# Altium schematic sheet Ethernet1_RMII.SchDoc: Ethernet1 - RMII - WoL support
size A3; Project: Project name; Date: Not used; ApprovedBy: Not used; CheckedBy: Not used; Author: Not used; CompanyName: STMicroelectronics; DrawnBy: Not used; Engineer: Not used; Organization: Not used; Address1: Not used; Address2: Not used; Address3: Not used; Address4: Not used; DocumentNumber: 7; Revision: Not used; SheetNumber: 7; SheetTotal: 17
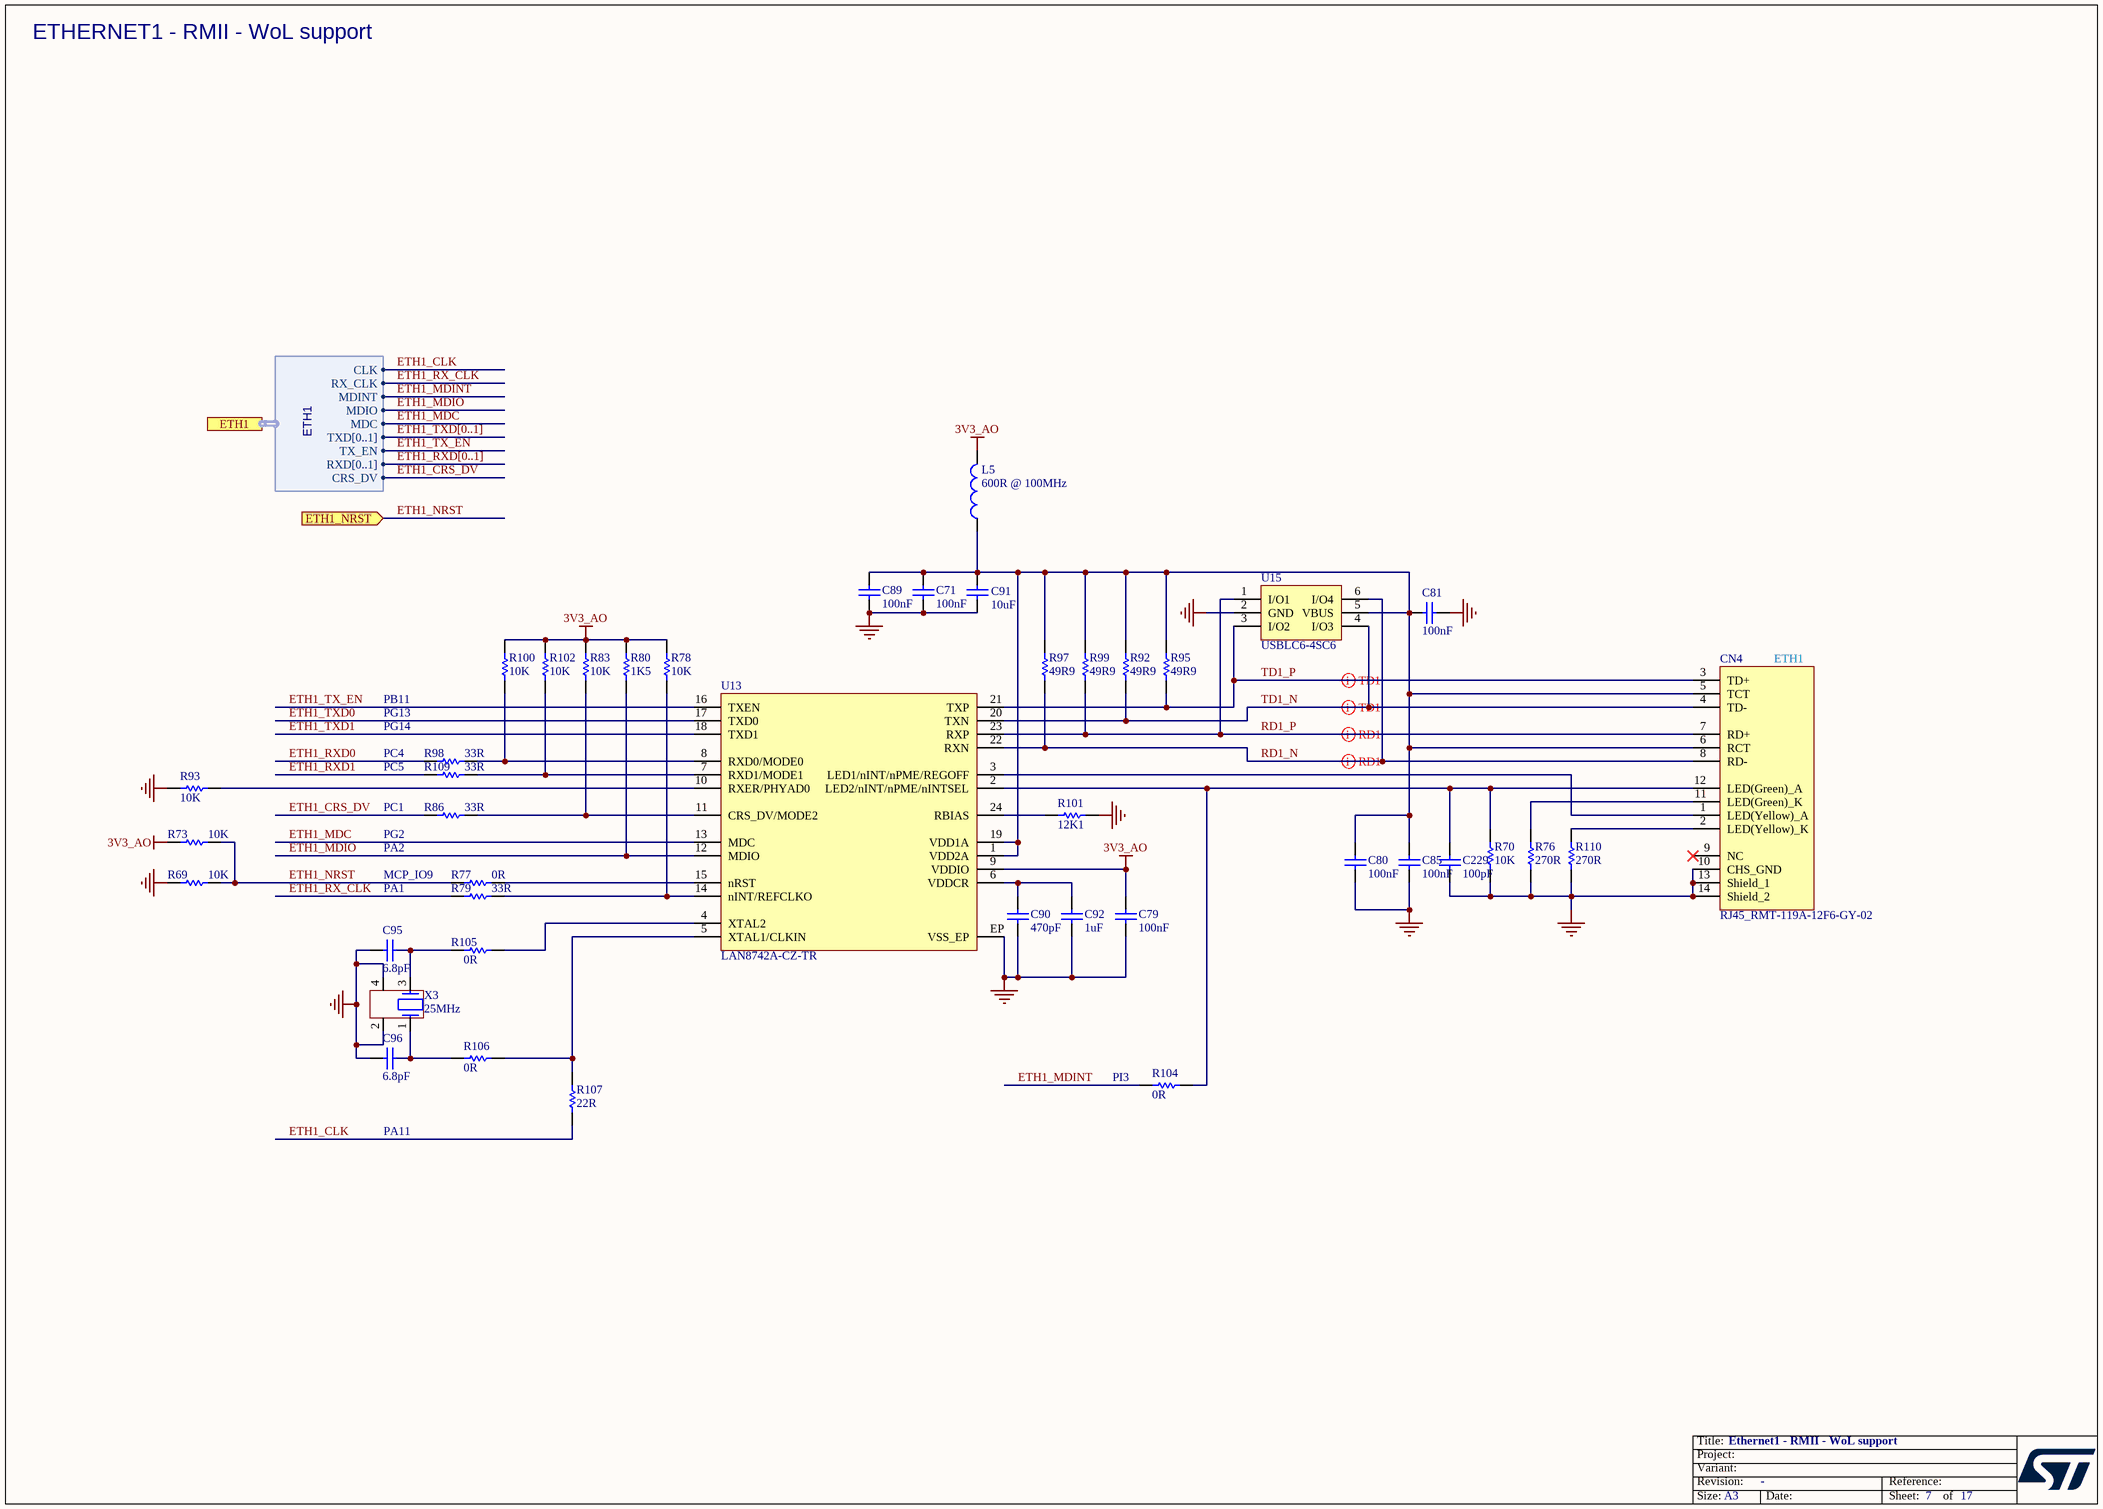
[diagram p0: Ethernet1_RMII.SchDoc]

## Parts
C71  value 100nF  [C0402]  (hidden comment: Capacitor)
C79  value 100nF  [C0402]  (hidden comment: Capacitor)
C80  value 100nF  [C0402]  (hidden comment: Capacitor)
C81  value 100nF  [C0402]  (hidden comment: Capacitor)
C85  value 100nF  [C0402]  (hidden comment: Capacitor)
C89  value 100nF  [C0402]  (hidden comment: Capacitor)
C90  value 470pF  [C0402]  (hidden comment: Capacitor)
C91  value 10uF  [C0603]  (hidden comment: Capacitor)
C92  value 1uF  [C0201_MURATA_GRM033_H0P3]  (hidden comment: Capacitor)
C95  value 6.8pF  [C0402]  (hidden comment: Capacitor)
C96  value 6.8pF  [C0402]  (hidden comment: Capacitor)
C229  value 100pF  [C0402]  (hidden comment: Capacitor)
CN4  value RJ45_RMT-119A-12F6-GY-02  [CON_RJ45_PHC_RMT-119A-12F6-GY-02]  (hidden comment: RJ45_RTS-119A-12F6-GY-02)
L5  value 600R @ 100MHz  [L0603]  (hidden comment: BEAD)
R69  value 10K  [R0402]  (hidden comment: Resistor)
R70  value 10K  [R0402]  (hidden comment: Resistor)
R73  value 10K  [R0402]  (hidden comment: Resistor)
R76  value 270R  [R0402]  (hidden comment: Resistor)
R77  value 0R  [R0402]  (hidden comment: Resistor)
R78  value 10K  [R0402]  (hidden comment: Resistor)
R79  value 33R  [R0402]  (hidden comment: Resistor)
R80  value 1K5  [R0402]  (hidden comment: Resistor)
R83  value 10K  [R0402]  (hidden comment: Resistor)
R86  value 33R  [R0402]  (hidden comment: Resistor)
R92  value 49R9  [R0402]  (hidden comment: Resistor)
R93  value 10K  [R0402]  (hidden comment: Resistor)
R95  value 49R9  [R0402]  (hidden comment: Resistor)
R97  value 49R9  [R0402]  (hidden comment: Resistor)
R98  value 33R  [R0402]  (hidden comment: Resistor)
R99  value 49R9  [R0402]  (hidden comment: Resistor)
R100  value 10K  [R0402]  (hidden comment: Resistor)
R101  value 12K1  [R0402]  (hidden comment: Resistor)
R102  value 10K  [R0402]  (hidden comment: Resistor)
R104  value 0R  [R0402]  (hidden comment: Resistor)
R105  value 0R  [R0402]  (hidden comment: Resistor)
R106  value 0R  [R0402]  (hidden comment: Resistor)
R107  value 22R  [R0402]  (hidden comment: Resistor)
R109  value 33R  [R0402]  (hidden comment: Resistor)
R110  value 270R  [R0402]  (hidden comment: Resistor)
U13  LAN8742A-CZ-TR  [ICC_VQFN24-EPAD_4X4_P050]
U15  USBLC6-4SC6  [ESD_SOT23-6L]
X3  value 25MHz  [CRY_NX2016SA_4P]  (hidden comment: XTAL_4_PINS)

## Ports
ETH1 (harness ETH1), ETH1_NRST (in)

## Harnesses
ETH1: MDINT, TXD[0..1], MDIO, MDC, RX_CLK, TX_EN, RXD[0..1], CRS_DV, CLK

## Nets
3V3_AO: C79.2 L5.2 R73.2 R78.2 R80.2 R83.2 R100.2 R102.2 U13.9(VDDIO)
GND: C71.1 C79.1 C80.1 C81.2 C85.1 C89.1 C90.1 C91.2 C92.1 C95.1 C96.1 C229.1 CN4.10(CHS_GND) CN4.13(Shield_1) CN4.14(Shield_2) R69.2 R70.1 R76.1 R93.2 R101.2 R110.1 U13.EP(VSS_EP) U15.2(GND) X3.2 X3.4
ETH1_CLK: R107.1 ; port ETH1.CLK
ETH1_CRS_DV: R86.1 ; port ETH1.CRS_DV
ETH1_MDC: U13.13(MDC) ; port ETH1.MDC
ETH1_MDINT: R104.1 ; port ETH1.MDINT
ETH1_MDIO: R80.1 U13.12(MDIO) ; port ETH1.MDIO
ETH1_NRST: R69.1 R73.1 R77.1 ; port ETH1_NRST
ETH1_RX_CLK: R79.1 ; port ETH1.RX_CLK
ETH1_RXD0: R98.1
ETH1_RXD1: R109.1
ETH1_TX_EN: U13.16(TXEN) ; port ETH1.TX_EN
ETH1_TXD0: U13.17(TXD0)
ETH1_TXD1: U13.18(TXD1)
RD1_N: CN4.8(RD-) R97.1 U13.22(RXN) U15.6(I/O4)
RD1_P: CN4.7(RD+) R99.1 U13.23(RXP) U15.1(I/O1)
TD1_N: CN4.4(TD-) R92.1 U13.20(TXN) U15.4(I/O3)
TD1_P: CN4.3(TD+) R95.1 U13.21(TXP) U15.3(I/O2)
NetC71_2: C71.2 C80.2 C81.1 C85.2 C89.2 C91.1 CN4.5(TCT) CN4.6(RCT) L5.1 R92.2 R95.2 R97.2 R99.2 U13.1(VDD2A) U13.19(VDD1A) U15.5(VBUS)
NetC90_2: C90.2 C92.2 U13.6(VDDCR)
NetC95_2: C95.2 R105.1 X3.3
NetC96_2: C96.2 R106.1 X3.1
NetC229_2: C229.2 CN4.12(LED(Green)_A) R70.2 R104.2 U13.2(LED2/nINT/nPME/nINTSEL)
NetCN4_1: CN4.1(LED(Yellow)_A) U13.3(LED1/nINT/nPME/REGOFF)
NetCN4_2: CN4.2(LED(Yellow)_K) R110.2
NetCN4_11: CN4.11(LED(Green)_K) R76.2
NetR77_2: R77.2 U13.15(nRST)
NetR78_1: R78.1 R79.2 U13.14(nINT/REFCLKO)
NetR83_1: R83.1 R86.2 U13.11(CRS_DV/MODE2)
NetR93_1: R93.1 U13.10(RXER/PHYAD0)
NetR98_2: R98.2 R100.1 U13.8(RXD0/MODE0)
NetR101_1: R101.1 U13.24(RBIAS)
NetR102_1: R102.1 R109.2 U13.7(RXD1/MODE1)
NetR105_2: R105.2 U13.4(XTAL2)
NetR106_2: R106.2 R107.2 U13.5(XTAL1/CLKIN)

Not connected (* = marked no-connect by the designer): CN4 9(NC)*

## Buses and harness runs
bus ETH1_RXD[0..1]
bus ETH1_TXD[0..1]

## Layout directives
differential pair: RD1_N, RD1_P, TD1_N, TD1_P

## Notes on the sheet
- ETHERNET1 - RMII - WoL support
- PB11
- PG13
- ETH1
- PC4
- PC5
- PG14
- PC1
- (near R86) PG2
- PA2
- PA1
- MCP_IO9
- (near R104) PI3
- PA11

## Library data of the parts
C71 C79-C81 C85 C89 = MCD-00006: Capacitor, MLCC, 100nF, 16V, X7R, +/-10%, 0402, T=0.5mm; Manufacturer_Part_Number: CC0402KRX7R7BB104; Manufacturer: YAGEO; Part_Preference: Recommended; Partial_Alternate_Internal_Part_Number: MCD-03299; Order_Code_RS: 9402047; Component_Country_Of_Origin: China; ShowFields: YES; ID: 2474
C90 = MCD-00724: Capacitor, MLCC, 470pF, 50V, NPO, +/-5%, 0402, T=0.5mm; Manufacturer_Part_Number: CC0402JRNPO9BN471; Manufacturer: YAGEO; Part_Preference: Recommended; Order_Code_RS: 199-2186; Component_Country_Of_Origin: China; ShowFields: YES; ID: 3023
C91 = MCD-00099: Capacitor, MLCC, 10uF, 10V, X5R, +/-10%, 0603, T=0.8mm; Manufacturer_Part_Number: GRM188R61A106KE69; Manufacturer: MURATA; Part_Preference: Recommended; Partial_Alternate_Internal_Part_Number: MCD-03152; Order_Code_RS: 2494233; Component_Country_Of_Origin: Japan°°; ShowFields: YES; ID: 2770
C92 = MCD-02377: Capacitor, MLCC, 1uF, 6.3V, X5R, +/-20%, 0201, T=0,3mm; Manufacturer_Part_Number: GRM033R60J105MEA2; Manufacturer: MURATA; Part_Preference: Recommended; Partial_Alternate_Internal_Part_Number: MCD-04356; Order_Code_RS: 820-0643; Component_Country_Of_Origin: Japan°; ShowFields: YES; ID: 4483
C95 C96 = MCD-00674: Capacitor, MLCC, 6.8pF, 50V, NPO, +/-0.25pF, 0402, T=0.5mm; Manufacturer_Part_Number: CC0402CRNPO9BN6R8; Manufacturer: YAGEO; Part_Preference: Recommended; Component_Country_Of_Origin: China; ShowFields: YES; ID: 3068
C229 = MCD-00205: Capacitor, MLCC, 100pF, 50V, NPO, +/-5%, 0402, T=0.5mm; Manufacturer_Part_Number: CC0402JRNPO9BN101; Manufacturer: YAGEO; Part_Preference: Recommended; Component_Country_Of_Origin: China; ShowFields: YES; ID: 2658
CN4 = MCD-02475: connector_RJ45, 10/100 Ethernet integrated MAG with integrate Green and Yellow LED, T= 13.61mm; Part_Preference: Recommended; Manufacturer: PENGHUI; Manufacturer_Part_Number: RMT-119A-12F6-GY-02; ShowFields: YES; ID: 4581; Component_Country_Of_Origin: China
L5 = MCD-00047: Ferrite bead, 600R @1 00MHz, +/-25%, 350mA, 0R5, 0603, T=0.8mm; Part_Type: Inductor; Manufacturer_Part_Number: FCM1608KF-601T03; Manufacturer: TAI-TECH; Part_Preference: Recommended; Partial_Alternate_Internal_Part_Number: MCD-02959; Component_Country_Of_Origin: Unknown; ShowFields: YES; ID: 2546
R69 R73 = MCD-00053: Resistor, 10K, 0402, +/-1%, 1/16W; Manufacturer_Part_Number: RC0402FR-0710KL; Manufacturer: YAGEO; Part_Preference: Recommended; BMS_Part_Number: 9131590; Order_Code_RS: 9239359; Component_Country_Of_Origin: China; ShowFields: YES; ID: 2539
R70 R78 R83 R93 R100 R102 = MCD-00053: Resistor, 10K, 0402, +/-1%, 1/16W; Manufacturer_Part_Number: RC0402FR-0710KL; Manufacturer: YAGEO; BMS_Part_Number: 9131590; Part_Preference: Recommended; Order_Code_RS: 9239359; Component_Country_Of_Origin: China; ShowFields: YES; ID: 2539
R76 R110 = MCD-00441: Resistor, 270R, 0402, +/-1%, 1/16W; Manufacturer_Part_Number: RC0402FR-07270RL; Manufacturer: YAGEO; Part_Preference: Recommended; Component_Country_Of_Origin: China; ShowFields: YES; ID: 2838
R77 = MCD-00052: Resistor, 0R, 0402, +/-5%, 1/16W; Part_Preference: Recommended; Manufacturer: YAGEO; Manufacturer_Part_Number: RC0402JR-070RL; Order_Code_RS: 9232516RL; Component_Country_Of_Origin: China; ShowFields: YES; ID: 2540
R79 R86 R98 R109 = MCD-00455: Resistor, 33R, 0402, +/-1%, 1/16W; Manufacturer_Part_Number: RC0402FR-0733RL; Manufacturer: YAGEO; Part_Preference: Recommended; Component_Country_Of_Origin: China; ShowFields: YES; ID: 2821
R80 = MCD-00068: Resistor, 1K5, 0402, +/-1%, 1/16W; Manufacturer_Part_Number: RC0402FR-071K5L; Manufacturer: YAGEO; Part_Preference: Recommended; Order_Code_RS: 9239251; Component_Country_Of_Origin: China; ShowFields: YES; ID: 2524
R92 R95 R97 R99 = MCD-00565: Resistor, 49R9, 0402, +/-1%, 1/16W; Manufacturer_Part_Number: RC0402FR-0749R9L; Manufacturer: YAGEO; Part_Preference: Recommended; Component_Country_Of_Origin: China; ShowFields: YES; ID: 3178
R101 = MCD-00723: Resistor, 12K1, 0402, +/-1%, 1/16W; Manufacturer_Part_Number: RC0402FR-0712K1L; Manufacturer: YAGEO; Part_Preference: Recommended; Component_Country_Of_Origin: China; ShowFields: YES; ID: 3022
R104-R106 = MCD-00052: Resistor, 0R, 0402, +/-5%, 1/16W; Manufacturer_Part_Number: RC0402JR-070RL; Manufacturer: YAGEO; Part_Preference: Recommended; Order_Code_RS: 9232516RL; Component_Country_Of_Origin: China; ShowFields: YES; ID: 2540
R107 = MCD-00189: Resistor, 22R, 0402, +/-1%, 1/16W; Manufacturer_Part_Number: RC0402FR-0722RL; Manufacturer: YAGEO; Part_Preference: Recommended; Component_Country_Of_Origin: China; ShowFields: YES; ID: 2677
U13 = MCD-00719: 10/100M RMII Ethernet transceiver; Part_Type: IC; Manufacturer: MICROCHIP; BMS_Part_Number: 9177984; Part_Preference: Recommended; Partial_Alternate_Internal_Part_Number: MCD-03200; Component_Country_Of_Origin: Unknown; ShowFields: YES; ID: 3026; Order_Code_RS: 215-3925
U15 = MCD-00250: Very low capacitance ESD protection , 4 lines; Part_Type: Diode; Manufacturer: STMICROELECTRONICS; BMS_Part_Number: 9151001; Part_Preference: Recommended; Manufacturer_HQ_COO: EU; Component_Country_Of_Origin: China; ShowFields: YES; ID: 2616; Order_Code_RS: 920-6272
X3 = MCD-01364: Crystal, 25MHz, 6pF, +/-20ppm, 80R, 2x1.6mm; BMS_Part_Number: 9157044; Part_Preference: Recommended; Part_Type: Crystal_Osc; Manufacturer: NDK; Manufacturer_Part_Number: NX2016SA-25MHZ-EXS00A-CS11321; Component_Country_Of_Origin: Japan; ShowFields: YES; ID: 3464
